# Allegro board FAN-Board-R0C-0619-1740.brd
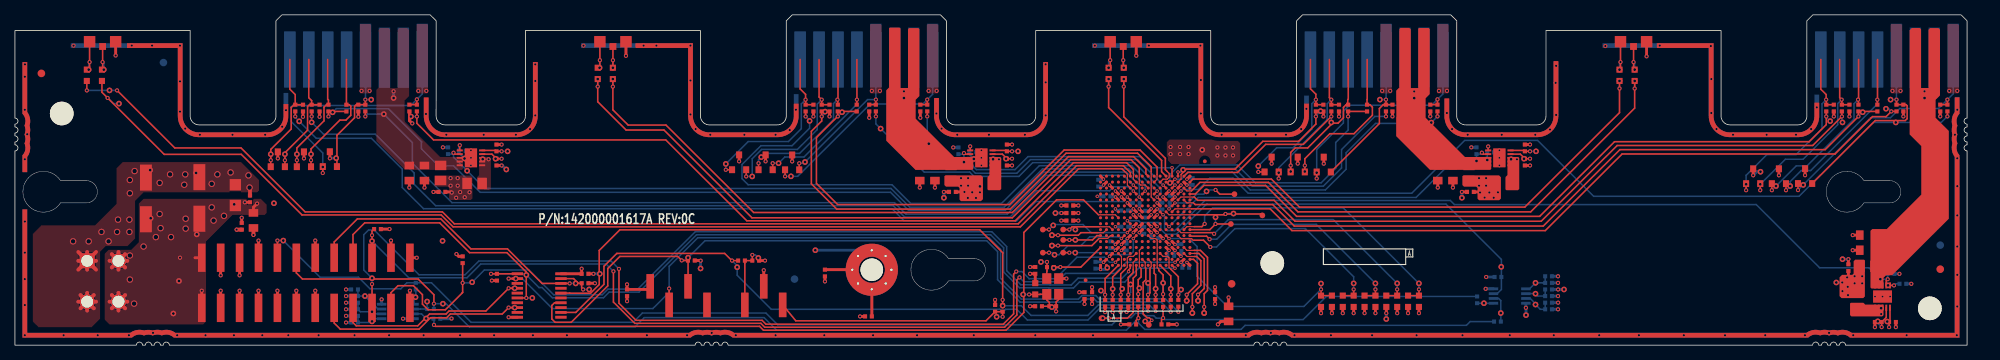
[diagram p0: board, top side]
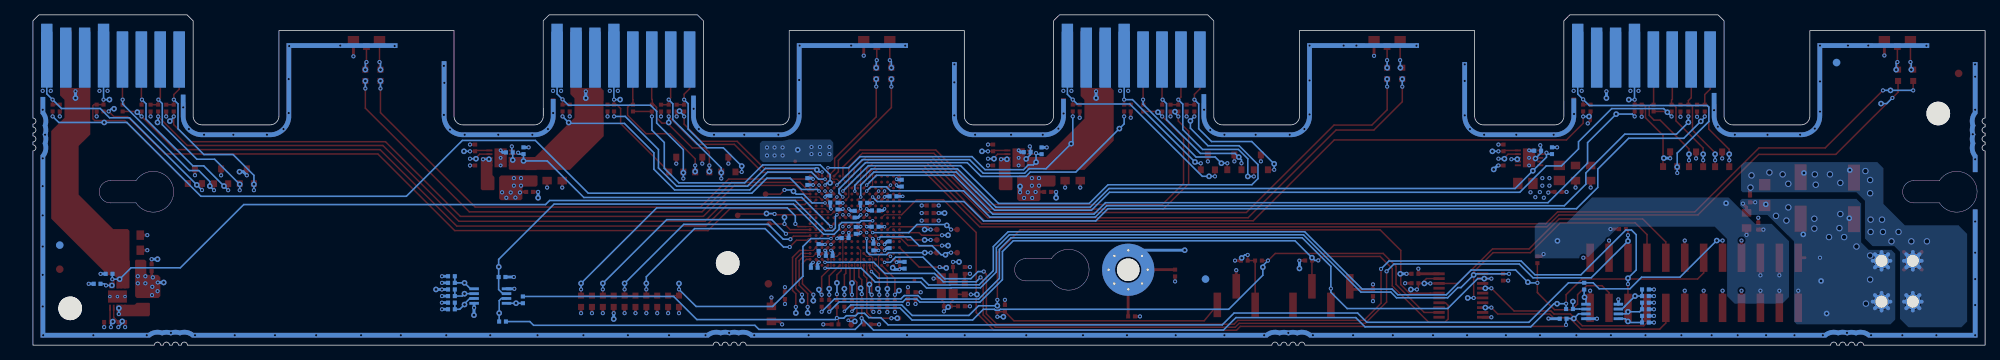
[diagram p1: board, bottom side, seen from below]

Outline 262.04 x 44.46 mm; copper layers: TOP, G2, V3, BOTTOM. Coordinates in mm from the lower left corner of the outline.

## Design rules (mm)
constraint set DEFAULT: min track width 0.203
net group CLS_CTRL-3W: nets CPLD_25MHZ CPLD_25MHZ_R FAN_SCL_1 FAN_SCL_1_R FAN_SDA_1 FAN_SDA_1_R
net group CLS_POWER: nets N66403123
net group CLS_VDD_12V: nets VDD12V

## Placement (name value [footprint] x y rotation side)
BGA1  LCMXO3LF-1300C-5BG256C  [BGA_D8_16C_256SP_14WL]  151.72 16.74 180 top
C1  0.1uF  [CC0402]  151.74 17.63 180 bottom
C2  0.1uF  [CC0402]  154.03 18.72 0 bottom
C3  0.1uF  [CC0402]  151.59 15.44 0 bottom
C4  0.1uF  [CC0402]  155.16 12.03 270 bottom
C5  10nF  [CC0402]  60.06 26.16 90 bottom
C6  10nF  [CC0402]  128.58 25.98 90 bottom
C7  10nF  [CC0402]  198.1 25.94 90 bottom
C8  0.1uF/16V  [CC0402]  64.64 24.64 180 top
C9  0.1uF/16V  [CC0402]  133.16 24.64 180 top
C10  0.1uF/16V  [CC0402]  202.69 24.64 180 top
C11  0.1uF  [CC0402]  150.52 19.15 90 bottom
C12  10uF  [CC0805]  52.95 23.16 0 top
C13  10uF  [CC0805]  54.98 23.16 0 top
C14  10uF  [CC0805]  121.46 23.16 0 top
C15  10uF  [CC0805]  123.49 23.16 0 top
C16  10uF  [CC0805]  191 23.16 0 top
C17  10uF  [CC0805]  193.03 23.16 0 top
C18  0.1uF  [CC0402]  31.56 19.68 0 top
C19  0.1uF  [CC0402]  158.09 22.02 180 bottom
C20  0.1uF  [CC0402]  148.96 18.12 90 bottom
C21  0.1uF/16V  [CC0402]  57.33 20.62 270 top
C22  0.1uF/16V  [CC0402]  125.84 20.62 270 top
C23  0.1uF/16V  [CC0402]  195.38 20.62 270 top
C24  0.1uF  [CC0402]  153.02 14.41 270 bottom
C25  0.1uF  [CC0402]  156.58 13.14 180 bottom
C26  0.1uF  [CC0402]  141.6 18.8 270 top
C27  270uF  [CAPALE_6D3PI_5D6_2SP_6D6WL7D6H]  17.59 19.75 180 top
C28  0.1uF  [CC0402]  147.07 13.51 180 bottom
C29  0.1uF  [CC0402]  141.6 17.78 270 top
C30  22uF  [CC0805]  32.02 16.79 180 top
C31  0.1uF  [CC0402]  141.6 16.76 270 top
C32  0.1uF  [CC0402]  149.22 13.21 0 bottom
C33  0.1uF  [CC0402]  30.45 16 180 top
C34  0.1uF  [CC0402]  155.02 19.66 180 bottom
C35  10uF  [CC0805]  248.65 14.81 270 top
C36  0.1uF  [CC0402]  149 15.94 90 bottom
C37  0.1uF  [CC0402]  157.16 10.43 90 bottom
C38  10uF  [CC0805]  248.65 12.78 270 top
C39  0.1uF  [CC0402]  145.05 10.76 0 bottom
C40  0.1uF  [CC0402]  146.6 20.03 90 bottom
C41  0.1uF/16V  [CC0402]  246.11 10.43 180 top
C42  10nF  [CC0402]  253.43 8.26 90 bottom
C43  0.1uF  [CC0402]  76.53 9.6 90 top
C44  10uF  [CC0805]  162.92 4.21 0 top
C45  0.1uF  [CC0402]  137.41 5.23 270 top
C46  0.1uF  [CC0402]  136.96 10.06 180 top
C47  0.1uF  [CC0402]  143.57 6.67 0 top
C48  0.1uF  [CC0402]  144.59 6.67 0 top
C49  0.1uF  [CC0402]  145.43 21.81 180 bottom
C50  1uF  [CC0402]  161.1 6.67 0 top
C51  0.1uF  [CC0402]  82.17 7.05 180 top
C52  0.1uF/16V  [CC0402]  250.13 3.11 90 top
C53  *270uF  [CAPALE_6D3PI_5D6_2SP_6D6WL7D6H]  24.77 19.81 180 top
C54  *22uF  [CC1206]  29.59 20.19 180 top
CONN1  LCB25-K2424S01C-03  [CONN_2D54X6D75_2X12SP_38D1W9L]  39.05 8.39 0 top
CONN2  MINI-FIT  [CONNF_4D2X5D5_2X2DP_10W9D6L_PIP]  11.8 8.6 180 top
CONN3  HXSPH2.54-S-S-08N5-G/F  [CONN_2D54X2D5_8SP_1NP_20D32W]  94.17 6.67 0 top
CONN4  gold_finger  [GOLD_FINGER_2D54_8X2SP]  36.9 38.45 180 bottom
CONN5  gold_finger  [GOLD_FINGER_2D54_8X2SP]  105.4 38.45 180 bottom
CONN6  gold_finger  [GOLD_FINGER_2D54_8X2SP]  173.9 38.45 180 bottom
CONN7  gold_finger  [GOLD_FINGER_2D54_8X2SP]  242.4 38.45 180 bottom
H7  SKREW  [MTH_276C118D_8DP_OSP]  115.02 10.15 90 top
L1  *100MHz/6A/30ohm  [LC0805]  57.15 23.18 180 top
L2  *100MHz/6A/30ohm  [LC0805]  125.67 23.18 180 top
L3  *100MHz/6A/30ohm  [LC0805]  195.2 23.18 180 top
L4  100MHz/6A/30ohm  [LC0805]  61.71 21.77 90 top
L5  100MHz/6A/30ohm  [LC0805]  130.23 21.77 90 top
L6  100MHz/6A/30ohm  [LC0805]  199.76 21.77 90 top
L7  *100MHz/6A/30ohm  [LC0805]  248.67 10.6 90 top
L8  100MHz/500mA  [LC0603]  136.96 7.58 180 top
L9  100MHz/6A/30ohm  [LC0805]  247.26 6.05 0 top
LED1  LED2_3  [LED_3D5_3SP_1W3L_A_C1_C2]  11.77 40.85 0 top
LED2  LED2_3  [LED_3D5_3SP_1W3L_A_C1_C2]  80.27 40.85 0 top
LED3  LED2_3  [LED_3D5_3SP_1W3L_A_C1_C2]  148.77 40.85 0 top
LED4  LED2_3  [LED_3D5_3SP_1W3L_A_C1_C2]  217.27 40.85 0 top
NOREF  -  []  160.52 41.66 0 top
NOREF#2  -  []  123.04 10.06 0 top
NOREF#3  -  []  0 0 0 top
NOREF#4  -  []  23.52 41.66 0 top
NOREF#5  -  []  7.7 5.85 0 top
NOREF#6  -  []  65.27 5.65 0 top
NOREF#7  -  []  205.52 41.66 0 top
NOREF#8  -  []  56.55 43.66 0 top
NOREF#9  -  []  240.54 43.66 0 top
NOREF#10  -  [unnamed#2]  163.32 8.26 0 top
NOREF#11  -  []  103.54 43.66 0 top
NOREF#12  -  []  172.04 43.66 0 top
NOREF#13  -  []  39.05 8.39 0 top
NOREF#14  -  []  7.57 20.65 0 top
NOREF#15  -  [unnamed#2]  6.29 31.18 0 top
NOREF#16  -  []  35.04 43.66 0 top
NOREF#17  -  []  37.05 8.39 0 top
NOREF#18  -  []  212.62 -88.02 0 top
NOREF#19  -  []  9.7 5.85 0 top
NOREF#20  -  []  115.02 10.15 0 top
NOREF#21  -  [unnamed#2]  258.44 10.22 0 top
NOREF#22  -  []  0 0 0 top
NOREF#23  -  []  70.69 18.92 0 top
NOREF#24  -  [unnamed#2]  257.05 4.95 0 top
NOREF#25  -  []  245.9 20.65 0 top
NOREF#26  -  []  92.02 41.66 0 top
NOREF#27  -  []  338.67 -98.03 0 top
NOREF#28  -  []  193.55 43.66 0 top
NOREF#29  -  []  3.82 20.65 0 top
NOREF#30  -  []  -30.48 -80.01 0 top
NOREF#31  -  []  65.27 5.65 0 top
NOREF#32  -  []  0 0 0 top
NOREF#33  -  []  262.04 43.66 0 top
NOREF#34  -  []  137.02 41.66 0 top
NOREF#35  -  [unnamed#2]  168.78 11.05 0 top
NOREF#36  -  []  246.02 20.5 0 top
NOREF#37  -  []  11.77 40.85 0 top
NOREF#38  -  []  148.77 40.85 0 top
NOREF#39  -  []  217.27 40.85 0 top
NOREF#40  -  []  229.02 41.66 0 top
NOREF#41  -  []  125.04 43.66 0 top
NOREF#42  -  [unnamed#2]  3.56 36.58 0 top
NOREF#43  -  []  68.52 41.66 0 top
NOREF#44  -  []  80.27 40.85 0 top
NOREF#45  -  []  115.02 10.15 0 top
NOREF#46  -  []  217.27 40.85 0 top
NOREF#47  -  [unnamed#2]  19.94 38.04 180 bottom
NOREF#48  -  [unnamed#2]  104.65 8.89 180 bottom
NOREF#49  -  [unnamed#2]  258.44 13.46 180 bottom
OSC1  25MHz  [OSC_1D6X2D12_4SP_2D5W3D2L1DH]  139.31 7.9 90 top
R1  110  [RC0603]  11.68 36.32 0 top
R2  110  [RC0603]  80.26 36.58 0 top
R3  110  [RC0603]  148.84 36.58 0 top
R4  110  [RC0603]  217.42 36.32 0 top
R5  110  [RC0603]  9.65 36.32 0 top
R6  110  [RC0603]  78.23 36.58 0 top
R7  110  [RC0603]  146.81 36.58 0 top
R8  110  [RC0603]  215.39 36.32 0 top
R9  1K  [RC0402]  47.04 31.92 0 top
R10  1K  [RC0402]  53.96 31.92 0 top
R11  1K  [RC0402]  115.57 31.92 0 top
R12  1K  [RC0402]  122.47 31.92 0 top
R13  1K  [RC0402]  184.04 31.92 0 top
R14  1K  [RC0402]  190.96 31.92 0 top
R15  1K  [RC0402]  252.57 31.92 0 top
R16  1K  [RC0402]  259.41 31.92 0 top
R17  1K  [RC0402]  37.63 31.91 0 top
R18  4.7K  [RC0402]  38.67 31.91 0 top
R19  1K  [RC0402]  39.83 31.91 0 top
R20  4.7K  [RC0402]  40.89 31.91 0 top
R21  470  [RC0402]  42.09 31.91 180 top
R22  470  [RC0402]  44.5 31.91 180 top
R23  1K  [RC0402]  106.14 31.91 0 top
R24  4.7K  [RC0402]  107.19 31.91 0 top
R25  1K  [RC0402]  108.3 31.91 0 top
R26  4.7K  [RC0402]  109.35 31.91 0 top
R27  470  [RC0402]  110.46 31.91 180 top
R28  470  [RC0402]  113 31.91 180 top
R29  1K  [RC0402]  174.63 31.91 0 top
R30  4.7K  [RC0402]  175.64 31.91 0 top
R31  1K  [RC0402]  176.7 31.91 0 top
R32  4.7K  [RC0402]  177.74 31.91 0 top
R33  470  [RC0402]  178.96 31.91 180 top
R34  470  [RC0402]  181.5 31.91 180 top
R35  1K  [RC0402]  243.14 31.91 0 top
R36  4.7K  [RC0402]  244.16 31.91 0 top
R37  1K  [RC0402]  245.24 31.91 0 top
R38  4.7K  [RC0402]  246.25 31.91 0 top
R39  470  [RC0402]  247.46 31.91 180 top
R40  470  [RC0402]  250 31.91 180 top
R43  2.2K 1%  [RC0402]  64.64 26.54 0 top
R44  2.2K 1%  [RC0402]  133.16 26.54 0 top
R45  2.2K 1%  [RC0402]  202.69 26.54 0 top
R46  *4.7K  [RC0402]  58.14 26.17 180 bottom
R47  *4.7K  [RC0402]  126.65 26.16 180 bottom
R48  *4.7K  [RC0402]  196.19 26.17 180 bottom
R57  1K  [RC0402]  48.67 15.62 270 top
R58  0  [RC0402]  108.73 9.71 180 top
R59  4.7K  [RC0402]  60.1 11.49 0 top
R61  4.7K  [RC0402]  90.81 11.39 90 top
R62  33  [RC0402]  97.54 11.38 90 top
R63  4.7K  [RC0402]  99.44 11.38 90 top
R64  *4.7K  [RC0402]  251.82 9.6 90 bottom
R65  4.7K  [RC0402]  139.31 5.23 90 top
R66  1K  [RC0402]  64.71 9.14 180 top
R67  33  [RC0402]  138.99 10.5 270 top
R68  4.7K  [RC0402]  76.53 8.33 270 top
R69  *10K  [RC0603]  175.32 5.91 0 top
R70  *4.7K  [RC0603]  176.78 5.91 180 top
R71  *10K  [RC0603]  178.24 5.91 0 top
R72  *4.7K  [RC0603]  179.71 5.91 180 top
R73  *10K  [RC0603]  181.17 5.91 0 top
R74  *4.7K  [RC0603]  182.63 5.91 180 top
R75  *10K  [RC0603]  184.09 5.91 0 top
R76  *4.7K  [RC0603]  185.55 5.91 180 top
R77  *10K  [RC0603]  187.01 5.91 0 top
R78  *4.7K  [RC0603]  188.47 5.91 180 top
R79  0  [RC0402]  114.58 3.87 90 top
R80  4.7K  [RC0402]  146.34 5.63 180 top
R81  4.7K  [RC0402]  147.36 5.63 180 top
R82  4.7K  [RC0402]  148.44 5.63 180 top
R83  4.7K  [RC0402]  149.45 5.63 180 top
R84  33  [RC0402]  150.79 5.63 180 top
R85  33  [RC0402]  152.11 5.63 0 top
R86  33  [RC0402]  153.12 5.63 0 top
R87  33  [RC0402]  155.15 5.63 0 top
R88  33  [RC0402]  156.17 5.63 0 top
R89  33  [RC0402]  154.13 5.61 180 top
R90  10K  [RC0402]  131.57 4.95 180 top
R91  33  [RC0402]  132.59 4.95 0 top
R93  2.2K 1%  [RC0402]  252.03 3.11 270 top
R94  4.7K  [RC0402]  150.05 2.79 270 top
R95  4.7K  [RC0402]  154.37 2.79 90 top
R96  4.7K  [RC0402]  199.08 9.17 270 bottom
R97  4.7K  [RC0402]  205.87 8.38 90 bottom
R98  4.7K  [RC0402]  205.87 7.49 90 bottom
R99  0  [RC0402]  53.82 7.94 180 bottom
R100  0  [RC0402]  196.28 6.1 180 bottom
R101  4.7K  [RC0402]  45.59 6.6 270 bottom
R102  4.7K  [RC0402]  205.87 4.83 270 bottom
R103  0  [RC0402]  55.79 4.86 90 bottom
R104  4.7K  [RC0402]  45.59 5.71 270 bottom
R105  0  [RC0402]  199.01 3.17 270 bottom
R106  4.7K  [RC0402]  56.64 3.56 90 bottom
R107  4.7K  [RC0402]  45.59 3.94 90 bottom
R108  4.7K  [RC0402]  184.91 31.92 0 top
R109  4.7K  [RC0402]  114.68 31.92 0 top
R110  4.7K  [RC0402]  46.1 31.92 0 top
R111  4.7K  [RC0402]  253.49 31.92 0 top
R112  4.7K  [RC0402]  189.99 31.92 0 top
R113  4.7K  [RC0402]  121.54 31.92 0 top
R114  4.7K  [RC0402]  52.96 31.92 0 top
R115  4.7K  [RC0402]  258.44 31.92 0 top
R116  *4.7K  [RC0402]  45.59 7.49 90 bottom
R117  *4.7K  [RC0402]  45.59 3.05 270 bottom
R118  *4.7K  [RC0402]  45.59 4.83 270 bottom
R119  *4.7K  [RC0402]  205.87 6.6 270 bottom
R120  *4.7K  [RC0402]  205.87 9.27 90 bottom
R121  *4.7K  [RC0402]  205.87 5.71 90 bottom
TP1  *NCA  [TP_30C0D0C_OSP]  167.45 17.46 0 top
TP2  *NCA  [TP_30C0D0C_OSP]  163.7 20.32 0 top
TP3  *NCA  [TP_30C0D0C_OSP]  137.99 15.56 180 top
TP4  *NCA  [TP_30C0D0C_OSP]  140.72 15.56 0 top
TP5  *NCA  [TP_30C0D0C_OSP]  163.22 16.31 0 top
TP6  *NCA  [TP_30C0D0C_OSP]  139.19 14.8 0 top
TP7  *NCA  [TP_30C0D0C_OSP]  140.72 14.16 180 top
TP8  *NCA  [TP_30C0D0C_OSP]  139.19 13.4 180 top
TP9  *NCA  [TP_30C0D0C_OSP]  137.99 12.45 180 top
TP10  *NCA  [TP_30C0D0C_OSP]  140.72 12.45 180 top
TP11  *NCA  [TP_30C0D0C_OSP]  157.29 5.97 0 top
TP12  *NCA  [TP_30C0D0C_OSP]  158.81 5.97 0 top
TP13  *NCA  [TP_30C0D0C_OSP]  158.05 4.32 0 top
TP14  *NCA  [TP_30C0D0C_OSP]  159.64 4.32 0 top
TP15  *NCA  [TP_30C0D0C_OSP]  145.86 3.62 180 top
TP16  *NCA  [TP_30C0D0C_OSP]  152.21 2.73 180 top
U1  SY6875ADBC  [DFN_D5X3D_10SP_3WL1H_G1]  61.21 25.21 90 top
U2  SY6875ADBC  [DFN_D5X3D_10SP_3WL1H_G1]  129.73 25.21 90 top
U3  SY6875ADBC  [DFN_D5X3D_10SP_3WL1H_G1]  199.26 25.21 90 top
U4  PSOT03C  [SOT23_1D9X2D_3SP_1D3W2D92L1D11H]  97.21 24.61 0 top
U5  PSOT03C  [SOT23_1D9X2D_3SP_1D3W2D92L1D11H]  100.77 24.61 0 top
U6  PSOT03C  [SOT23_1D9X2D_3SP_1D3W2D92L1D11H]  104.33 24.6 0 top
U7  PSOT03C  [SOT23_1D9X2D_3SP_1D3W2D92L1D11H]  168.69 24.31 0 top
U8  PSOT03C  [SOT23_1D9X2D_3SP_1D3W2D92L1D11H]  172.2 24.31 0 top
U9  PSOT03C  [SOT23_1D9X2D_3SP_1D3W2D92L1D11H]  175.69 24.31 0 top
U10  PSOT03C  [SOT23_1D9X2D_3SP_1D3W2D92L1D11H]  42.28 25.03 0 top
U11  PSOT03C  [SOT23_1D9X2D_3SP_1D3W2D92L1D11H]  35.29 25.02 0 top
U12  PSOT03C  [SOT23_1D9X2D_3SP_1D3W2D92L1D11H]  38.8 25.02 0 top
U13  PSOT03C  [SOT23_1D9X2D_3SP_1D3W2D92L1D11H]  240.3 22.75 0 top
U14  PSOT03C  [SOT23_1D9X2D_3SP_1D3W2D92L1D11H]  233.33 22.74 0 top
U15  PSOT03C  [SOT23_1D9X2D_3SP_1D3W2D92L1D11H]  236.79 22.74 0 top
U16  SN74LVC244APWR  [TSSOP_D65X5D88_20SP_6D5L]  70.37 6.68 0 top
U17  SY6875ADBC  [DFN_D5X3D_10SP_3WL1H_G1]  250.7 6.54 0 top
U18  TMP75AIDGK  [SOP_D65X4D35_8SP_3WL]  200.65 6.61 0 bottom
U19  TMP75AIDGK  [SOP_D65X4D35_8SP_3WL]  51.4 4.53 180 bottom

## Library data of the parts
BGA1 = CPLD_LATTICE_LCMXO3L_caBGA256
C1-C7 C11-C20 C24-C26 C28-C40 C42 C44-C51 C54 = C_NP
C8-C10 C21-C23 C41 C52 = CAP NP: room: 35
C27 C53 = C_P
C43 = C_NP: room: 71
CONN1 = PIN HEADER_MALE_12PX2R
CONN2 = CONN_POWER_FEMALE_2PX2R
CONN3 = PINSTICK_MALE_8PX1R_VOID5
CONN4-CONN7 = CONN_2
H7 = SKREW
L1-L9 = BEAD: room: 8
LED1-LED4 = LED2_3
OSC1 = OSC_10
R1-R8 = R_0: room: 55
R9-R17 R19 R23 R25 R29 R31 R35 R37 R46-R48 R57-R59 R64 R66-R68 R79 R84-R90 R94-R107 R116-R121 = R: tolerance: 1%
R18 R20 R24 R26 R30 R32 R36 R38 R43-R45 R62 R69 R71 R73 R75 R77 R91 R93 R108-R115 = R
R21 R22 R27 R28 R33 R34 R39 R40 = R: room: 1
R61 R63 R65 R70 R72 R74 R76 R78 R80-R83 = R: tolerance: 1%; room: U83
TP1-TP16 = NCA: room: 9
U1-U3 U17 = MONITOR_CUR_SILERGY_SY6875
U4-U15 = TVS3_1
U16 = LOGIC_TI_SN74LVC244A
U18 U19 = TEMP SENSOR_TI_TMP75

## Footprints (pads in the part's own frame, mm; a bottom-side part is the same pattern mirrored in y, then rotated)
BGA_D8_16C_256SP_14WL
  round 0.508 smd: (-8,-8) (8,8)
  round 0.406 smd: A1(-6,6) A2(-5.2,6) A3(-4.4,6) A4(-3.6,6) A5(-2.8,6) A6(-2,6) A7(-1.2,6) A8(-0.4,6) A9(0.4,6) A10(1.2,6) A11(2,6) A12(2.8,6) A13(3.6,6) A14(4.4,6) A15(5.2,6) A16(6,6) B1(-6,5.2) B2(-5.2,5.2) B3(-4.4,5.2) B4(-3.6,5.2) B5(-2.8,5.2) B6(-2,5.2) B7(-1.2,5.2) B8(-0.4,5.2) B9(0.4,5.2) B10(1.2,5.2) B11(2,5.2) B12(2.8,5.2) B13(3.6,5.2) B14(4.4,5.2) B15(5.2,5.2) B16(6,5.2) C1(-6,4.4) C2(-5.2,4.4) C3(-4.4,4.4) C4(-3.6,4.4) C5(-2.8,4.4) C6(-2,4.4) C7(-1.2,4.4) C8(-0.4,4.4) C9(0.4,4.4) C10(1.2,4.4) C11(2,4.4) C12(2.8,4.4) C13(3.6,4.4) C14(4.4,4.4) C15(5.2,4.4) C16(6,4.4) D1(-6,3.6) D2(-5.2,3.6) D3(-4.4,3.6) D4(-3.6,3.6) D5(-2.8,3.6) D6(-2,3.6) D7(-1.2,3.6) D8(-0.4,3.6) D9(0.4,3.6) D10(1.2,3.6) D11(2,3.6) D12(2.8,3.6) D13(3.6,3.6) D14(4.4,3.6) D15(5.2,3.6) D16(6,3.6) E1(-6,2.8) E2(-5.2,2.8) E3(-4.4,2.8) E4(-3.6,2.8) E5(-2.8,2.8) E6(-2,2.8) E7(-1.2,2.8) E8(-0.4,2.8) E9(0.4,2.8) E10(1.2,2.8) E11(2,2.8) E12(2.8,2.8) E13(3.6,2.8) E14(4.4,2.8) E15(5.2,2.8) E16(6,2.8) F1(-6,2) F2(-5.2,2) F3(-4.4,2) F4(-3.6,2) F5(-2.8,2) F6(-2,2) F7(-1.2,2) F8(-0.4,2) F9(0.4,2) F10(1.2,2) F11(2,2) F12(2.8,2) F13(3.6,2) F14(4.4,2) F15(5.2,2) F16(6,2) G1(-6,1.2) G2(-5.2,1.2) G3(-4.4,1.2) G4(-3.6,1.2) G5(-2.8,1.2) G6(-2,1.2) G7(-1.2,1.2) G8(-0.4,1.2) G9(0.4,1.2) G10(1.2,1.2) G11(2,1.2) G12(2.8,1.2) G13(3.6,1.2) G14(4.4,1.2) G15(5.2,1.2) G16(6,1.2) H1(-6,0.4) H2(-5.2,0.4) H3(-4.4,0.4) H4(-3.6,0.4) H5(-2.8,0.4) H6(-2,0.4) H7(-1.2,0.4) H8(-0.4,0.4) H9(0.4,0.4) H10(1.2,0.4) H11(2,0.4) H12(2.8,0.4) H13(3.6,0.4) H14(4.4,0.4) H15(5.2,0.4) H16(6,0.4) J1(-6,-0.4) J2(-5.2,-0.4) J3(-4.4,-0.4) J4(-3.6,-0.4) J5(-2.8,-0.4) J6(-2,-0.4) J7(-1.2,-0.4) J8(-0.4,-0.4) J9(0.4,-0.4) J10(1.2,-0.4) J11(2,-0.4) J12(2.8,-0.4) J13(3.6,-0.4) J14(4.4,-0.4) J15(5.2,-0.4) J16(6,-0.4) K1(-6,-1.2) K2(-5.2,-1.2) K3(-4.4,-1.2) K4(-3.6,-1.2) K5(-2.8,-1.2) K6(-2,-1.2) K7(-1.2,-1.2) K8(-0.4,-1.2) K9(0.4,-1.2) K10(1.2,-1.2) K11(2,-1.2) K12(2.8,-1.2) K13(3.6,-1.2) K14(4.4,-1.2) K15(5.2,-1.2) K16(6,-1.2) L1(-6,-2) L2(-5.2,-2) L3(-4.4,-2) L4(-3.6,-2) L5(-2.8,-2) L6(-2,-2) L7(-1.2,-2) L8(-0.4,-2) L9(0.4,-2) L10(1.2,-2) L11(2,-2) L12(2.8,-2) L13(3.6,-2) L14(4.4,-2) L15(5.2,-2) L16(6,-2) M1(-6,-2.8) M2(-5.2,-2.8) M3(-4.4,-2.8) M4(-3.6,-2.8) M5(-2.8,-2.8) M6(-2,-2.8) M7(-1.2,-2.8) M8(-0.4,-2.8) M9(0.4,-2.8) M10(1.2,-2.8) M11(2,-2.8) M12(2.8,-2.8) M13(3.6,-2.8) M14(4.4,-2.8) M15(5.2,-2.8) M16(6,-2.8) N1(-6,-3.6) N2(-5.2,-3.6) N3(-4.4,-3.6) N4(-3.6,-3.6) N5(-2.8,-3.6) N6(-2,-3.6) N7(-1.2,-3.6) N8(-0.4,-3.6) N9(0.4,-3.6) N10(1.2,-3.6) N11(2,-3.6) N12(2.8,-3.6) N13(3.6,-3.6) N14(4.4,-3.6) N15(5.2,-3.6) N16(6,-3.6) P1(-6,-4.4) P2(-5.2,-4.4) P3(-4.4,-4.4) P4(-3.6,-4.4) P5(-2.8,-4.4) P6(-2,-4.4) P7(-1.2,-4.4) P8(-0.4,-4.4) P9(0.4,-4.4) P10(1.2,-4.4) P11(2,-4.4) P12(2.8,-4.4) P13(3.6,-4.4) P14(4.4,-4.4) P15(5.2,-4.4) P16(6,-4.4) R1(-6,-5.2) R2(-5.2,-5.2) R3(-4.4,-5.2) R4(-3.6,-5.2) R5(-2.8,-5.2) R6(-2,-5.2) R7(-1.2,-5.2) R8(-0.4,-5.2) R9(0.4,-5.2) R10(1.2,-5.2) R11(2,-5.2) R12(2.8,-5.2) R13(3.6,-5.2) R14(4.4,-5.2) R15(5.2,-5.2) R16(6,-5.2) T1(-6,-6) T2(-5.2,-6) T3(-4.4,-6) T4(-3.6,-6) T5(-2.8,-6) T6(-2,-6) T7(-1.2,-6) T8(-0.4,-6) T9(0.4,-6) T10(1.2,-6) T11(2,-6) T12(2.8,-6) T13(3.6,-6) T14(4.4,-6) T15(5.2,-6) T16(6,-6)
CAPALE_6D3PI_5D6_2SP_6D6WL7D6H
  rect 1.6x3.505 smd: A(0,-2.8) C(0,2.8)
CC0402
  rect 0.559x0.539 smd: 1(0,0.454) 2(0,-0.454)
CC0805
  rect 1.27x1.016 smd: 1(0,1.016) 2(0,-1.016)
CC1206
  rect 1.524x1.524 smd: 1(0,1.397) 2(0,-1.397)
CONN_2D54X2D5_8SP_1NP_20D32W
  rect 1.016x3.302 smd: 1(-8.89,1.25) 2(-6.35,-1.25) 3(-3.81,1.25) 4(-1.27,-1.25) 6(3.81,-1.25) 7(6.35,1.25) 8(8.89,-1.25)
CONN_2D54X6D75_2X12SP_38D1W9L
  rect 1.016x3.81 smd: 1(-13.97,-3.375) 2(-13.97,3.375) 3(-11.43,-3.375) 4(-11.43,3.375) 5(-8.89,-3.375) 6(-8.89,3.375) 7(-6.35,-3.375) 8(-6.35,3.375) 9(-3.81,-3.375) 10(-3.81,3.375) 11(-1.27,-3.375) 12(-1.27,3.375) 13(1.27,-3.375) 14(1.27,3.375) 15(3.81,-3.375) 16(3.81,3.375) 17(6.35,-3.375) 18(6.35,3.375) 19(8.89,-3.375) 20(8.89,3.375) 21(11.43,-3.375) 22(11.43,3.375) 23(13.97,-3.375) 24(13.97,3.375)
CONNF_4D2X5D5_2X2DP_10W9D6L_PIP
  rect 2.032x2.032 hole 1.6: 1(2.1,-2.75)
  round 2.032 hole 1.6: 2(-2.1,-2.75) 3(2.1,2.75) 4(-2.1,2.75)
DFN_D5X3D_10SP_3WL1H_G1
  rect 0.254x0.813 smd: 1(-1,-1.5) 2(-0.5,-1.5) 3(0,-1.5) 4(0.5,-1.5) 5(1,-1.5) 6(1,1.5) 7(0.5,1.5) 8(0,1.5) 9(-0.5,1.5) 10(-1,1.5)
  rect 2.54x1.651 smd: G1(0,0)
GOLD_FINGER_2D54_8X2SP
  rect 1.524x7.518 smd: 1(0,0) 2(-2.54,0) 3(-5.08,0) 4(-7.62,0) 9(0,0) 10(-2.54,0) 11(-5.08,0) 12(-7.62,0) 13(-10.16,0) 14(-12.7,0) 15(-15.24,0) 16(-17.78,0)
  rect 1.524x8.56 smd: 5(-10.16,0.533) 8(-17.78,0.533)
  rect 1.524x8.052 smd: 6(-12.7,0.267) 7(-15.24,0.267)
LC0603
  rect 0.813x0.813 smd: 1(0,0.762) 2(0,-0.762)
LC0805
  rect 1.524x1.27 smd: 1(0,1.016) 2(0,-1.016)
LED_3D5_3SP_1W3L_A_C1_C2
  rect 1.524x1.524 smd: A(1.75,0) C1(-1.75,0)
  rect 0.914x0.914 smd: C2(0,-0.65)
MTH_276C118D_8DP_OSP
  round 2.997 hole 2.997 unplated: (0,0)
  round 0.889 hole 0.305: 1(0,2.629) 2(1.859,1.859) 3(2.629,0) 4(1.859,-1.859) 5(0,-2.629) 6(-1.859,-1.859) 7(-2.629,0) 8(-1.859,1.859)
OSC_1D6X2D12_4SP_2D5W3D2L1DH
  rect 1.422x1.219 smd: 1(-1.06,-0.8) 2(1.06,-0.8) 3(1.06,0.8) 4(-1.06,0.8)
RC0402
  rect 0.559x0.539 smd: 1(0,0.454) 2(0,-0.454)
RC0603
  rect 0.813x0.813 smd: 1(0,0.762) 2(0,-0.762)
SOP_D65X4D35_8SP_3WL
  rect 1.27x0.381 smd: 1(-2.175,0.975) 2(-2.175,0.325) 3(-2.175,-0.325) 4(-2.175,-0.975) 5(2.175,-0.975) 6(2.175,-0.325) 7(2.175,0.325) 8(2.175,0.975)
SOT23_1D9X2D_3SP_1D3W2D92L1D11H
  rect 0.813x0.914 smd: A(0,1) C1(-0.95,-1) C2(0.95,-1)
TP_30C0D0C_OSP
  round 0.762 smd: 1(0,0)
TSSOP_D65X5D88_20SP_6D5L
  rect 1.524x0.381 smd: 1(-2.926,2.926) 2(-2.926,2.276) 3(-2.926,1.626) 4(-2.926,0.975) 5(-2.926,0.325) 6(-2.926,-0.325) 7(-2.926,-0.975) 8(-2.926,-1.626) 9(-2.926,-2.276) 10(-2.926,-2.926) 11(2.926,-2.926) 12(2.926,-2.276) 13(2.926,-1.626) 14(2.926,-0.975) 15(2.926,-0.325) 16(2.926,0.325) 17(2.926,0.975) 18(2.926,1.626) 19(2.926,2.276) 20(2.926,2.926)
unnamed#2
  round 1.016 smd: (0,0)

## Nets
GND: BGA1.B2(GND/GND/GND_1) BGA1.B15(GND/GND/GND_2) BGA1.C3(GND/GND/GND_3) BGA1.C14(GND/GND/GND_4) BGA1.D4(GND/GND/GND_5) BGA1.D13(GND/GND/GND_6) BGA1.E5(GND/GND/GND_7) BGA1.E12(GND/GND/GND_8) BGA1.F6(GND/GND/GND_9) BGA1.F11(GND/GND/GND_10) BGA1.H8(GND/GND/GND_11) BGA1.H9(GND/GND/GND_12) BGA1.J8(GND/GND/GND_13) BGA1.J9(GND/GND/GND_14) BGA1.L6(GND/GND/GND_15) BGA1.L11(GND/GND/GND_16) BGA1.M5(GND/GND/GND_17) BGA1.M12(GND/GND/GND_18) BGA1.N4(GND/GND/GND_19) BGA1.N13(GND/GND/GND_20) BGA1.P3(GND/GND/GND_21) BGA1.P14(GND/GND/GND_22) BGA1.R2(GND/GND/GND_23) BGA1.R15(GND/GND/GND_24) C1.2 C2.2 C3.2 C4.2 C5.1 C6.1 C7.1 C8.1 C9.1 C10.1 C11.2 C12.2 C13.2 C14.2 C15.2 C16.2 C17.2 C18.2 C19.2 C20.2 C21.2 C22.2 C23.2 C24.2 C25.2 C26.2 C27.C C28.2 C29.2 C30.2 C31.2 C32.2 C33.2 C34.2 C35.2 C36.2 C37.2 C38.2 C39.2 C40.2 C41.2 C42.1 C43.2 C44.2 C45.2 C46.2 C47.2 C48.2 C49.2 C50.2 C51.1 C52.1 C53.C C54.1 CONN1.1 CONN1.2 CONN1.7 CONN1.8 CONN1.9 CONN1.11 CONN1.13 CONN1.14 CONN1.22 CONN1.23 CONN1.24 CONN2.2 CONN2.4 CONN3.7 CONN4.5(C5) CONN4.8(C8) CONN5.5(C5) CONN5.8(C8) CONN6.5(C5) CONN6.8(C8) CONN7.5(C5) CONN7.8(C8) OSC1.2(GND) R43.1 R44.1 R45.1 R58.1 R69.2 R71.2 R73.2 R75.2 R77.2 R79.1 R90.2 R93.1 R98.1 R101.1 R117.1 R118.1 R120.1 R121.1 U1.G1 U2.G1 U3.G1 U4.A U5.A U6.A U7.A U8.A U9.A U10.A U11.A U12.A U13.A U14.A U15.A U16.10(GND) U17.G1 U18.4(GND) U19.4(GND)
VCC_12P_FAN1: C16.1 C17.1 CONN6.6(C6) CONN6.7(C7) L3.2 U3.8(OUT8) U3.9(OUT9) U3.10(OUT0)
VCC_12P_FAN2: C14.1 C15.1 CONN5.6(C6) CONN5.7(C7) L2.2 U2.8(OUT8) U2.9(OUT9) U2.10(OUT0)
VCC_12P_FAN3: C12.1 C13.1 CONN4.6(C6) CONN4.7(C7) L1.2 U1.8(OUT8) U1.9(OUT9) U1.10(OUT0)
VCC_12P_FAN4: C35.1 C38.1 CONN7.6(C6) CONN7.7(C7) L7.2 U17.8(OUT8) U17.9(OUT9) U17.10(OUT0)
VCC_CL_FAN1: L6.2 U3.1(IN1) U3.2(IN2) U3.3(IN3)
VCC_CL_FAN2: L5.2 U2.1(IN1) U2.2(IN2) U2.3(IN3)
VCC_CL_FAN3: L4.2 U1.1(IN1) U1.2(IN2) U1.3(IN3)
VCC_CL_FAN4: L9.2 U17.1(IN1) U17.2(IN2) U17.3(IN3)
VDD12V: C18.1 C21.1 C22.1 C23.1 C27.A C41.1 C53.A C54.2 CONN2.1 CONN2.3 L1.1 L2.1 L3.1 L4.1 L5.1 L6.1 L7.1 L9.1
25MHZ_EN: OSC1.1(\\S\T/OE) R65.2
BOARD_ID_1: BGA1.F3(PL4A/PL7A/PL8A) R71.1 R72.2
BOARD_ID_2: BGA1.F1(PL4B/PL7B/PL8B) R73.1 R74.2
CPLD_25MHZ: BGA1.D16(PR2A/PR3A/PR3A || R_GPLLT_IN**) R67.1
CPLD_25MHZ_R: OSC1.3(OUT) R67.2
CPLD_TCK: BGA1.A7(PT16C/PT15C/PT17C || TCK) R86.1
CPLD_TDI: BGA1.A6(PT12D/PT13D/PT14D || TDI) R87.1
CPLD_TDO: BGA1.C6(PT12C/PT13C/PT14C || TDO) R88.1
CPLD_TMS: BGA1.B8(PT16D/PT15D/PT17D || TMS) R85.1
CPLD_UPD_DISABLE: BGA1.A4(PT10A*/PT10A*/PT10A*) R66.2 U16.1(1O\\\E)
EN_FAN1: BGA1.H5(PL9C/PL13C/PL15C) R48.2 U3.7(EN)
EN_FAN2: BGA1.T4(PB3B/PB3B/PB4B) R47.2 U2.7(EN)
EN_FAN3: BGA1.N9(PB16D/PB18B/PB21B) R46.2 U1.7(EN)
EN_FAN4: BGA1.K6(PL10D/PL14D/PL16D) R64.2 U17.7(EN)
FAN1_DET: BGA1.R4(PB6D/PB6B/PB7B) R14.2
FAN1_DET_R: CONN6.16(C16) R14.1 R112.1 U9.C1
FAN1_DIR: BGA1.T3(PB6C/PB6A/PB7A) R13.2
FAN1_DIR_R: CONN6.13(C13) R13.1 R108.1 U9.C2
FAN1_IN_PWM: CONN6.4(C4) R34.2 U8.C2
FAN1_LED_G: BGA1.R6(PB6B/PB7B/PB9B) R3.2
FAN1_LED_G_R: LED3.C2 R3.1
FAN1_LED_R: BGA1.T5(PB6A/PB7A/PB9A) R7.2
FAN1_LED_R_R: LED3.C1 R7.1
FAN1_OUT_PWM: CONN6.3(C3) R33.2 U8.C1
FAN1_PWM: BGA1.P4(PB3A/PB3A/PB4A) R33.1 R34.1
FAN1_SENSOR: BGA1.T2(PB3C/PB3C/PB4C) R31.2
FAN1_SENSOR_R: CONN6.2(C2) R31.1 R32.1 U7.C2
FAN1_VCP: C10.2 U3.4(VCP)
FAN1R_SENSOR: BGA1.R3(PB3D/PB3D/PB4D) R29.2
FAN1R_SENSOR_R: CONN6.1(C1) R29.1 R30.1 U7.C1
FAN2_DET: BGA1.P5(PB5B/PB4B/PB6B) R12.2
FAN2_DET_R: CONN5.16(C16) R12.1 R113.1 U6.C1
FAN2_DIR: BGA1.M6(PB11C/PB12A/PB15A) R11.2
FAN2_DIR_R: CONN5.13(C13) R11.1 R109.1 U6.C2
FAN2_IN_PWM: CONN5.4(C4) R28.2 U5.C2
FAN2_LED_G: BGA1.T8(PB12B/PB15B/PB18B) R2.2
FAN2_LED_G_R: LED2.C2 R2.1
FAN2_LED_R: BGA1.P8(PB12A/PB15A/PB18A) R6.2
FAN2_LED_R_R: LED2.C1 R6.1
FAN2_OUT_PWM: CONN5.3(C3) R27.2 U5.C1
FAN2_PWM: BGA1.R7(PB9A/PB10A/PB13A) R27.1 R28.1
FAN2_SENSOR: BGA1.M7(PB9C/PB10C/PB13C) R25.2
FAN2_SENSOR_R: CONN5.2(C2) R25.1 R26.1 U4.C2
FAN2_VCP: C9.2 U2.4(VCP)
FAN2R_SENSOR: BGA1.N7(PB9D/PB10D/PB13D) R23.2
FAN2R_SENSOR_R: CONN5.1(C1) R23.1 R24.1 U4.C1
FAN3_DET: BGA1.R10(PB19B/PB23B/PB29B) R10.2
FAN3_DET_R: CONN4.16(C16) R10.1 R114.1 U10.C1
FAN3_DIR: BGA1.P10(PB19A/PB23A/PB29A) R9.2
FAN3_DIR_R: CONN4.13(C13) R9.1 R110.1 U10.C2
FAN3_IN_PWM: CONN4.4(C4) R22.2 U12.C2
FAN3_LED_G: BGA1.P11(PB21B/PB24B/PB31B) R1.2
FAN3_LED_G_R: LED1.C2 R1.1
FAN3_LED_R: BGA1.T11(PB21A/PB24A/PB31A) R5.2
FAN3_LED_R_R: LED1.C1 R5.1
FAN3_OUT_PWM: CONN4.3(C3) R21.2 U12.C1
FAN3_PWM: BGA1.M9(PB18C/PB21C/PB26C) R21.1 R22.1
FAN3_SENSOR: BGA1.N10(PB19C/PB23C/PB28A) R19.2
FAN3_SENSOR_R: CONN4.2(C2) R19.1 R20.1 U11.C2
FAN3_VCP: C8.2 U1.4(VCP)
FAN3R_SENSOR: BGA1.M11(PB19D/PB23D/PB28B) R17.2
FAN3R_SENSOR_R: CONN4.1(C1) R17.1 R18.1 U11.C1
FAN4_DET: BGA1.N3(PL14B/PL20B/PL25B) R16.2
FAN4_DET_R: CONN7.16(C16) R16.1 R115.1 U13.C1
FAN4_DIR: BGA1.K4(PL11C/PL16C/PL19C) R15.2
FAN4_DIR_R: CONN7.13(C13) R15.1 R111.1 U13.C2
FAN4_IN_PWM: CONN7.4(C4) R40.2 U15.C2
FAN4_LED_G: BGA1.P2(PL14D/PL20D/PL25D) R4.2
FAN4_LED_G_R: LED4.C2 R4.1
FAN4_LED_R: BGA1.R1(PL14C/PL20C/PL25C) R8.2
FAN4_LED_R_R: LED4.C1 R8.1
FAN4_OUT_PWM: CONN7.3(C3) R39.2 U15.C1
FAN4_PWM: BGA1.M2(PL14A/PL20A/PL25A) R39.1 R40.1
FAN4_SENSOR: BGA1.M3(PL13A/PL19A/PL24A) R37.2
FAN4_SENSOR_R: CONN7.2(C2) R37.1 R38.1 U14.C2
FAN4_VCP: C52.2 U17.4(VCP)
FAN4R_SENSOR: BGA1.N1(PL13B/PL19B/PL24B) R35.2
FAN4R_SENSOR_R: CONN7.1(C1) R35.1 R36.1 U14.C1
FAN_IDLE: BGA1.A11(PT21A*/PT24A*/PT28A*) CONN1.21 R59.2
FAN_INTERRUPT: BGA1.B13(PT22C/PT26A*/PT34A*) CONN1.19
FAN_SCL_1: CONN1.12 R84.1 R94.1 R103.1 R105.1
FAN_SCL_1_R: BGA1.D9(PT18B*/PT20B*/PT22B*) R84.2
FAN_SDA_1: CONN1.10 R89.1 R95.1 R99.1 R100.1
FAN_SDA_1_R: BGA1.F8(PT18A*/PT20A*/PT22A*) R89.2
FANCARD_CPLD_TCK: CONN1.17 U16.4(1A2)
FANCARD_CPLD_TCK_Y: R86.2 R91.1 U16.16(1Y2)
FANCARD_CPLD_TDI: CONN1.18 U16.6(1A3)
FANCARD_CPLD_TDI_Y: CONN3.3 R61.1 R87.2 U16.14(1Y3)
FANCARD_CPLD_TDO: CONN1.16 U16.18(1Y1)
FANCARD_CPLD_TDO_Y: CONN3.2 R88.2 U16.2(1A1)
FANCARD_CPLD_TMS: CONN1.15 U16.8(1A4)
FANCARD_CPLD_TMS_Y: R62.1 R85.2 U16.12(1Y4)
FANCARD_RST_N: BGA1.B3(PT9C/PT9C/PT9C) CONN1.20 R57.2
ILIM_FAN1: R45.2 U3.5(ILIM)
ILIM_FAN2: R44.2 U2.5(ILIM)
ILIM_FAN3: R43.2 U1.5(ILIM)
ILIM_FAN4: R93.2 U17.5(ILIM)
JTAG_TCK_R: CONN3.8 R90.1 R91.2
JTAG_TMS_R: CONN3.6 R62.2 R63.1
SST_FAN1: C7.2 U3.6(SST)
SST_FAN2: C6.2 U2.6(SST)
SST_FAN3: C5.2 U1.6(SST)
SST_FAN4: C42.2 U17.6(SST)
TEMP_SENSOR_ALERT_1: BGA1.H11(PR9C/PR13C/PR16C) R96.2 U18.3(ALERT)
TEMP_SENSOR_ALERT_2: BGA1.J13(PR9D/PR13D/PR16D) R106.2 U19.3(ALERT)
VERSION_ID_1: BGA1.G2(PL5A/PL8A/PL9A) R77.1 R78.2
VERSION_ID_2: BGA1.G3(PL5B/PL8B/PL9B) R75.1 R76.2
VERSION_ID_3: BGA1.F5(PL5C/PL8C/PL9C) R69.1 R70.2
VSTB_3V3: BGA1.A1(VCC/VCC/VCC_1) BGA1.A16(VCC/VCC/VCC_2) BGA1.D5(VCCIO0/VCCIO0/VCCIO0_1) BGA1.D12(VCCIO0/VCCIO0/VCCIO0_2) BGA1.E4(VCCIO5/VCCIO5/VCCIO5) BGA1.E13(VCCIO1/VCCIO1/VCCIO1_1) BGA1.G7(VCC/VCC/VCC_3) BGA1.G8(VCCIO0/VCCIO0/VCCIO0_3) BGA1.G9(VCCIO0/VCCIO0/VCCIO0_4) BGA1.G10(VCC/VCC/VCC_4) BGA1.H7(VCCIO4/VCCIO4/VCCIO4_1) BGA1.H10(VCCIO1/VCCIO1/VCCIO1_2) BGA1.J7(VCCIO4/VCCIO4/VCCIO4_2) BGA1.J10(VCCIO1/VCCIO1/VCCIO1_3) BGA1.K7(VCC/VCC/VCC_5) BGA1.K8(VCCIO2/VCCIO2/VCCIO2_1) BGA1.K9(VCCIO2/VCCIO2/VCCIO2_2) BGA1.K10(VCC/VCC/VCC_6) BGA1.M4(VCCIO3/VCCIO3/VCCIO3) BGA1.M13(VCCIO1/VCCIO1/VCCIO1_4) BGA1.N5(VCCIO2/VCCIO2/VCCIO2_3) BGA1.N12(VCCIO2/VCCIO2/VCCIO2_4) BGA1.T1(VCC/VCC/VCC_7) BGA1.T16(VCC/VCC/VCC_8) C1.1 C2.1 C3.1 C4.1 C11.1 C19.1 C20.1 C24.1 C25.1 C26.1 C28.1 C29.1 C30.1 C31.1 C32.1 C33.1 C34.1 C36.1 C37.1 C39.1 C40.1 C43.1 C44.1 C46.1 C47.1 C48.1 C49.1 C50.1 C51.2 CONN1.3 CONN1.4 CONN1.5 CONN1.6 CONN3.1 L8.2 LED1.A LED2.A LED3.A LED4.A R18.2 R20.2 R24.2 R26.2 R30.2 R32.2 R36.2 R38.2 R46.1 R47.1 R48.1 R57.1 R59.1 R61.2 R63.2 R64.1 R66.1 R68.1 R70.1 R72.1 R74.1 R76.1 R78.1 R80.1 R81.1 R82.1 R83.1 R94.2 R95.2 R96.1 R97.1 R102.2 R104.1 R106.1 R107.2 R108.2 R109.2 R110.2 R111.2 R112.2 R113.2 R114.2 R115.2 R116.2 R119.2 U16.20(VCC) U18.8(VCC) U19.8(VCC)
VSTB_3V3_25M_VCC: C45.1 L8.1 OSC1.4(VDD) R65.1
N66403123: H7.1 H7.2 H7.3 H7.4 H7.5 H7.6 H7.7 H7.8 R58.2 R79.2
N66410905: R105.2 U18.2(SCL)
N66410909: R100.2 U18.1(SDA)
N66410919: R103.2 U19.2(SCL)
N66410923: R99.2 U19.1(SDA)
N66487659: R68.2 U16.19(2O\\\E)
N66707807: BGA1.C10(PT20C/PT23C/PT27C || JTAGENB) R82.2
N66707810: BGA1.B10(PT20D/PT23D/PT27D || PROGRAMN) R83.2
N66708102: BGA1.A13(PT24C/PT28C/PT36C || INITN) R80.2
N66708112: BGA1.C13(PT24D/PT28D/PT36D || DONE) R81.2
N66771338: BGA1.B9(PT19A*/PT21A*/PT25A*) TP16.1
N66771341: BGA1.A10(PT19B*/PT21B*/PT25B*) TP15.1
N66771344: BGA1.F10(PT21C/PT24C/PT32A*) TP10.1
N66771524: BGA1.F12(PR4C/PR6C/PR7C) TP9.1
N66771539: BGA1.G11(PR5C/PR8C/PR10C) TP3.1
N66771544: BGA1.F14(PR4A/PR6A/PR7A) TP8.1
N66771549: BGA1.F16(PR4B/PR6B/PR7B) TP7.1
N66771572: BGA1.G14(PR5B/PR8B/PR9B) TP4.1
N66771573: BGA1.G15(PR5A/PR8A/PR9A) TP6.1
N66771601: BGA1.K5(PL12C/PL17C/PL21C) TP1.1
N66771603: BGA1.L4(PL12D/PL17D/PL21D) TP2.1
N66771664: BGA1.C2(PL1D/PL2D/PL2D) TP13.1
N66771666: BGA1.B1(PL1C/PL2C/PL2C) TP11.1
N66771757: BGA1.D2(PL2D/PL4D/PL4D) TP14.1
N66771759: BGA1.C1(PL2C/PL4C/PL4C) TP12.1
N66771796: BGA1.G1(PL6A/PL9A/PL10A) TP5.1
N66862681: R107.1 R117.2 U19.5(A2)
N66863023: R104.2 R118.2 U19.6(A1)
N66863106: R101.2 R116.1 U19.7(A0)
N66867929: R97.2 R120.2 U18.5(A2)
N66867942: R98.2 R119.1 U18.6(A1)
N66868149: R102.1 R121.2 U18.7(A0)

Pads without a net: BGA1 A2 A3 A5 A8 A9 A12 A14 A15 B4 B5 B6 B7 B11 B12 B14 B16 C4 C5 C7 C8 C9 C11 C12 C15 C16 D1 D3 D6 D7 D8 D10 D11 D14 D15 E1 E2 E3 E6 E7 E8 E9 E10 E11 E14 E15 E16 F2 F4 F7 F9 F13 F15 G4 G5 G6 G12 G13 G16 H1 H2 H3 H4 H6 H12 H13 H14 H15 H16 J1 J2 J3 J4 J5 J6 J11 J12 J14 J15 J16 K1 K2 K3 K11 K12 K13 K14 K15 K16 L1 L2 L3 L5 L7 L8 L9 L10 L12 L13 L14 L15 L16 M1 M8 M10 M14 M15 M16 N2 N6 N8 N11 N14 N15 N16 P1 P6 P7 P9 P12 P13 P15 P16 R5 R8 R9 R11 R12 R13 R14 R16 T6 T7 T9 T10 T12 T13 T14 T15; CONN3 4; CONN4 9 10 11 12 14 15; CONN5 9 10 11 12 14 15; CONN6 9 10 11 12 14 15; CONN7 9 10 11 12 14 15; U16 3 5 7 9 11 13 15 17

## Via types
v1: diameter 0.762, hole 0.381, TOP to BOTTOM, 174 vias
v2: diameter 0.457, hole 0.254, TOP to BOTTOM, 83 vias
v3: diameter 0.559, hole 0.305, TOP to BOTTOM, 511 vias
v4: diameter 0.864, hole 0.61, TOP to BOTTOM, 33 vias
v5: diameter 0.508, hole 0.254, TOP to BOTTOM, 9 vias

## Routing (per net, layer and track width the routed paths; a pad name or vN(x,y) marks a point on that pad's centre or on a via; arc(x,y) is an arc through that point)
GND: length 165.4
  TOP w0.381: BGA1.R15 v2(146.13,21.55) ; BGA1.F11 v2(149.33,14.35) ; BGA1.N13 v2(147.73,20.74) ; C33.2 v3(30.45,17.14) ; CONN1.8 v3(32.7,14.08) ; U8.A v3(172.2,24.43) ; C51.1 v3(82.17,5.92) ; U12.A v3(38.8,25.13) ; C8.1 v3(65.33,24.18) ; U4.A v3(97.21,24.74) ; BGA1.D4 v2(155.72,12.75) ; R79.1 v3(113.45,3.87) ; C46.2 v3(136.27,10.51) ; R73.2 v3(181.17,4.31) ; CONN1.13 v3(40.32,7.33) ; C47.2 v3(143.57,5.54) ; R90.2 v3(131.57,6.1) ; R44.1 v3(133.85,27) ; BGA1.M5 v2(154.13,19.94) ; BGA1.J9 v2(150.93,17.54) ; C26.2 v3(140.46,18.8) ; C52.1 v3(249.67,2.43) ; R45.1 v3(203.38,27) ; U15.A v3(236.79,22.86) ; R69.2 v3(175.32,4.31) ; BGA1.L11 v2(149.33,19.14) ; C30.2 32.02,18.56 v3(32.51,19.05) ; C44.2 161.88,3.19 v3(161.48,2.79) ; C15.2 v3(123.49,21.21) ; BGA1.H8 v2(152.52,15.95) ; C23.2 v3(194.23,20.62) ; CONN3.7 v3(100.52,10.08) ; BGA1.E5 v2(154.92,13.55) ; R77.2 v3(187.01,4.31) ; U10.A v3(42.28,25.15) ; OSC1.2 v3(141.15,8.96) ; U6.A v3(104.33,24.73) ; C9.1 v3(133.85,24.18) ; C12.2 v3(52.95,21.21) ; R93.1 v3(252.49,2.43) ; C16.2 v3(191,21.21) ; U14.A v3(233.33,22.86) ; BGA1.N4 v2(155.72,20.74) ; C45.2 v3(136.27,5.23) ; C13.2 v3(54.98,21.21) ; R71.2 v3(178.24,4.31) ; CONN1.1 v3(25.08,7.33) ; BGA1.E12 v2(148.53,13.55) ; CONN1.14 v3(40.32,14.08) ; U16.10 v3(66.28,3.75) ; C50.2 v3(161.1,5.54) ; BGA1.P3 v2(156.52,21.54) ; CONN1.2 24.17,11.76 ; v3(30.86,19.23) C18.2 ; U5.A v3(100.77,24.74) ; BGA1.D13 v2(147.73,12.75) ; BGA1.R2 v2(157.32,21.55) ; U13.A v3(240.3,22.88) ; R43.1 v3(65.33,27) ; C43.2 v3(77.66,9.6) ; BGA1.M12 v2(148.53,19.94) ; CONN1.23 v3(53.02,7.33) ; U9.A v3(175.69,24.43) ; BGA1.B2 v2(156.53,11.15) ; C38.2 v3(246.7,12.78) ; C21.2 v3(56.18,20.62) ; C48.2 v3(144.59,5.54) ; R58.1 v3(108.73,8.58) ; BGA1.C3 v2(156.52,11.95) ; R75.2 v3(184.09,4.31) ; BGA1.C14 v2(146.93,11.95) ; C41.2 v3(246.11,11.57) ; BGA1.F6 v2(154.12,14.35) ; CONN1.9 v3(35.24,7.33) ; C29.2 v3(140.46,17.78) ; C22.2 v3(124.7,20.62) ; CONN1.22 v3(50.48,14.08) ; BGA1.J8 v2(152.52,17.54) ; CONN1.7 v3(32.7,7.33) ; U11.A v3(35.29,25.13) ; CONN1.11 v3(37.78,7.33) ; BGA1.L6 v2(153.33,19.14) ; BGA1.H9 v2(150.93,15.95) ; BGA1.B15 v2(146.13,11.15) ; C14.2 v3(121.46,21.21) ; CONN1.24 v3(53.93,11.76) ; C31.2 v3(140.46,16.76) ; C17.2 v3(193.03,21.21) ; C35.2 v3(246.7,14.81) ; BGA1.P14 v2(146.93,21.54) ; C10.1 v3(203.38,24.18) ; U7.A v3(168.69,24.43)
  TOP w0.508: 12.71,11.35 CONN2.2 ; CONN2.2 13,12.25 ; CONN2.2 13,10.45 ; CONN2.2 14.8,12.25 ; CONN2.2 13.9,10.16 ; CONN2.2 15.09,11.35 ; CONN2.2 14.8,10.45 ; CONN2.2 13.9,12.54 ; 13.9,4.66 CONN2.4 ; CONN2.4 14.8,6.75 ; CONN2.4 13.9,7.04 ; CONN2.4 13,4.95 ; CONN2.4 14.8,4.95 ; CONN2.4 13,6.75 ; CONN2.4 12.71,5.85 ; CONN2.4 15.09,5.85
  G2 w0.381: CONN2.4 15.09,5.85 ; CONN2.4 12.71,5.85 ; CONN2.4 13.9,4.66 ; CONN2.4 13.9,7.04 ; 12.71,11.35 CONN2.2 ; CONN2.2 13.9,10.16 ; CONN2.2 13.9,12.54 ; CONN2.2 15.09,11.35
  BOTTOM w0.381: C40.2 v2(145.29,20.03) ; v5(129.73,26.22) 129.48,25.98 C6.1 ; v2(156.53,11.15) 156.71,10.97 C37.2 ; v5(61.21,26.22) 61.15,26.16 C5.1 ; v3(233.33,22.86) 233.82,23.34 v1(234.31,23.34) ; R121.1 v3(207.15,5.71) ; v1(124.7,19.83) v3(124.7,20.62) ; v2(156.52,11.95) 156.58,12.01 C25.2 ; C4.2 155.61,12.64 v2(155.72,12.75) ; v2(149.33,19.14) 149.34,19.15 C11.2 ; C7.1 198.98,25.94 v5(199.26,26.22) ; v2(154.12,14.35) 154.06,14.41 C24.2 ; v2(147.73,12.75) 147.42,13.06 C28.2 ; R101.1 v3(44.45,6.6) ; v3(65.33,24.18) 65.43,24.18 v1(65.96,23.65) ; C32.2 149.22,14.24 v2(149.33,14.35) ; R98.1 v3(207.15,7.49) v1(207.94,7.49) ; v3(42.28,25.15) 42.3,25.17 v1(43.13,25.17) ; C2.2 153.36,19.17 v2(153.33,19.14) ; C3.2 150.98,15.9 v2(150.93,15.95) ; C42.1 v3(254.56,8.26) ; C39.2 146.07,11.21 v2(146.13,11.15) ; R120.1 v3(207.14,9.27) ; U18.4 v3(197.43,7.58) ; v1(78.51,9.6) v3(77.66,9.6) ; v2(154.91,18.34) 155.02,18.44 C34.2 ; v2(157.32,21.55) 157.34,21.57 C19.2 ; v2(147.73,18.34) 147.94,18.12 C20.2 ; R118.1 v3(44.45,4.83) ; v1(184.09,3.51) v3(184.09,4.31) ; v1(245.32,11.57) v3(246.11,11.57) ; R117.1 v3(44.45,3.05) ; C36.2 v2(147.73,15.94) ; v2(150.93,17.54) 151.3,17.17 C1.2 ; v1(194.23,19.83) v3(194.23,20.62) ; v1(139.67,17.78) v3(140.46,17.78) ; v2(146.13,21.55) 145.93,21.35 C49.2 ; U19.4 v3(52.1,3.56)
  BOTTOM w0.508: 13,10.45 CONN2.2 ; CONN2.2 13.9,10.16 ; CONN2.2 12.71,11.35 ; CONN2.2 13.9,12.54 ; CONN2.2 13,12.25 ; CONN2.2 14.8,10.45 ; CONN2.2 14.8,12.25 ; CONN2.2 15.09,11.35 ; CONN2.4 14.8,6.75 ; CONN2.4 12.71,5.85 ; CONN2.4 13,6.75 ; CONN2.4 13.9,4.66 ; CONN2.4 14.8,4.95 ; CONN2.4 13.9,7.04 ; CONN2.4 13,4.95 ; CONN2.4 15.09,5.85
  vias: v1(18.22,17.08) v1(21.27,4.25) v1(22.02,8.64) v1(24.41,14.91) v1(29.44,18.95) v2(249.68,6.54) v2(250.7,6.54) v2(251.71,6.54) v3(1.35,37.8) v3(1.33,36.13) v3(1.33,31.69) v3(1.33,25.02) v3(1.33,16.64) v3(1.33,12.45) v3(1.33,8.89) v3(1.33,5.4) v3(1.33,1.33) v3(1.65,28.38) v3(6.54,1.33) v3(7.87,40.31) v3(11.11,1.33) v3(15.3,1.33) v3(15.68,40.32) v3(18.41,40.32) v3(18.54,1.65) v3(21.78,1.33) v3(22.16,40.32) v3(22.16,35.5) v3(22.16,31.43) v3(22.17,11.76) v3(22.86,29.15) v3(24.83,28.32) v3(25.59,1.33) v3(29.21,28.32) v3(29.4,1.33) v3(33.21,1.33) v3(33.59,28.32) v3(35.88,29.4) v3(36.39,31.62) v3(36.7,1.33) v3(40.77,1.33) v3(45.59,1.33) v3(46.53,34.23) v3(47.61,34.23) v3(50.23,1.33) v3(54.15,34.23) v3(54.86,1.33) v3(55.23,34.23) v3(55.18,31.11) v3(57.91,28.32) v3(59.75,1.33) v3(62.93,28.32) v3(64.33,1.33) v3(67.25,28.32) v3(69.15,29.08) v3(69.53,1.33) v3(69.85,37.8) v3(69.85,35.56) v3(69.85,30.92) v3(74.1,1.33) v3(76.33,40.31) v3(79.5,1.33) v3(84.39,40.32) v3(84.84,1.33) v3(86.11,40.32) v3(90.23,1.33) v3(90.68,40.32) v3(90.68,35.62) v3(90.68,31.05) v3(91.38,29.08) v3(93.34,28.32) v3(93.54,1.65) v3(96.77,1.33) v3(97.92,28.32) v3(102.11,28.32) v3(102.11,1.33) v3(104.01,28.96) v3(104.84,31.69) v3(108.65,1.33) v3(115.03,34.23) v3(115.19,1.33) v3(116.11,34.23) v3(121.09,1.33) v3(122.65,34.23) v3(123.73,34.23) v3(123.7,31.18) v3(124.4,29.15) v3(126.49,28.32) v3(128.71,1.33) v3(130.75,28.32) v3(135.57,28.32) v3(136.97,1.33) v3(138.35,37.8) v3(138.37,35.37) v3(138.37,30.92) v3(144.72,1.33) v3(144.96,40.31) v3(150.69,1.33) v3(152.21,40.32) v3(157.92,1.33) v3(159.13,40.32) v3(159.19,35.69) v3(159.19,31.18) v3(161.99,28.32) v3(165.23,1.33) v3(166.56,28.32) v3(168.59,1.65) v3(170.62,28.32) v3(171.77,1.33) v3(172.66,29.08) v3(173.35,31.81) v3(176.66,1.33) v3(182.18,1.33) v3(183.53,34.23) v3(184.61,34.23) v3(188.15,1.33) v3(191.15,34.23) v3(192.23,34.23) v3(192.21,31.24) v3(192.91,29.08) v3(194.31,1.33) v3(195.01,28.32) v3(199.58,28.32) v3(200.66,1.33) v3(204.09,28.32) v3(206.06,29.02) v3(206.57,1.33) v3(206.82,35.31) v3(206.88,37.59) v3(206.88,30.99) v3(212.66,1.33) v3(213.49,40.26) v3(218,1.33) v3(220.79,40.32) v3(224.03,1.33) v3(227.65,40.26) v3(227.71,35.81) v3(227.71,31.24) v3(228.41,29.08) v3(229.55,1.33) v3(230.63,28.32) v3(234.95,1.33) v3(235.14,28.32) v3(239.08,28.32) v3(240.28,1.33) v3(241.11,29.08) v3(241.87,32) v3(243.52,1.65) v3(246.76,1.33) v3(252.03,34.23) v3(253.11,34.23) v3(253.94,1.33) v3(259.65,34.23) v3(260.41,28.32) v3(260.73,34.23) v3(260.73,31.69) v3(260.73,25.15) v3(260.73,21.4) v3(260.73,17.46) v3(260.73,13.27) v3(260.73,9.46) v3(260.73,5.21) v3(260.67,1.33) v4(15.43,12.06) v4(15.43,8.83) v4(16,5.59) v4(17.27,13.27) v4(18.92,14.54) v4(19.43,17.65) v4(19.56,15.75) v4(20.95,14.54) v4(22.92,17.02) v4(22.92,15.68) v4(26.42,18.54) v4(26.67,16.76) v4(28.07,17.4) v5(61.21,25.21) v5(61.21,24.19) v5(129.73,25.21) v5(129.73,24.19) v5(199.26,25.21) v5(199.26,24.19)
VCC_12P_FAN1: length 0.9
  BOTTOM w0.381: v3(187.83,34.15) v1(187.83,33.25)
VCC_12P_FAN2: length 0.9
  BOTTOM w0.381: v3(119.33,34.16) v1(119.33,33.26)
VCC_12P_FAN3: length 0.9
  BOTTOM w0.381: v3(50.83,34.16) v1(50.83,33.26)
VCC_12P_FAN4: length 0.9
  BOTTOM w0.381: v3(256.33,34.16) v1(256.33,33.26)
VCC_CL_FAN1: length 0.8
  BOTTOM w0.203: v1(200.83,25.02) 201.62,25.02 v3(201.62,25.02)
VCC_CL_FAN2: length 0.8
  BOTTOM w0.203: v3(132.09,25.02) 132.09,25.02 v1(131.3,25.02)
VCC_CL_FAN3: length 0.8
  BOTTOM w0.203: v3(63.58,25.02) 63.58,25.03 v1(62.79,25.03)
VCC_CL_FAN4: length 0.8
  BOTTOM w0.203: v1(250.51,4.97) v3(250.51,4.18)
VDD12V: length 67.3
  TOP w0.381: v3(245.95,9.12) 246.11,9.28 C41.1 ; C22.1 v3(127.46,20.62) ; v3(58.64,20.54) 58.55,20.62 C21.1 ; C23.1 196.6,20.62 v3(196.67,20.55)
  TOP w0.508: 8.51,10.16 CONN2.1 ; CONN2.1 9.7,12.54 ; CONN2.1 10.89,12.54 ; CONN2.1 10.89,10.16 ; CONN2.1 8.51,11.35 ; CONN2.1 8.51,12.54 ; CONN2.1 9.7,10.16 ; CONN2.1 10.89,11.35 ; CONN2.3 9.7,7.04 ; CONN2.3 8.8,6.75 ; CONN2.3 10.89,5.85 ; CONN2.3 9.7,4.66 ; CONN2.3 10.6,6.75 ; CONN2.3 8.51,5.85 ; CONN2.3 8.8,4.95 ; CONN2.3 10.6,4.95 ; v4(31.5,21.21) 31.56,21.15 C18.1
  V3 w0.508: 8.51,11.35 CONN2.1 ; CONN2.1 9.7,12.54 ; CONN2.1 8.8,12.25 ; CONN2.1 10.6,12.25 ; CONN2.1 10.89,11.35 ; CONN2.1 9.7,10.16 ; CONN2.1 10.6,10.45 ; CONN2.1 8.8,10.45 ; CONN2.3 10.6,4.95 ; CONN2.3 8.8,4.95 ; CONN2.3 10.89,5.85 ; CONN2.3 9.7,4.66 ; CONN2.3 8.8,6.75 ; CONN2.3 10.6,6.75 ; CONN2.3 9.7,7.04 ; CONN2.3 8.51,5.85
  BOTTOM w0.381: v3(245.29,8.43) v1(244.49,8.43) ; v3(129.54,20.57) v1(129.54,21.37)
  BOTTOM w0.508: 8.51,5.85 CONN2.3 ; CONN2.3 10.6,6.75 ; CONN2.3 10.89,5.85 ; CONN2.3 10.6,4.95 ; CONN2.3 8.8,4.95 ; CONN2.3 8.8,6.75 ; CONN2.3 9.7,7.04 ; CONN2.3 9.7,4.66 ; 8.8,12.25 CONN2.1 ; CONN2.1 9.7,12.54 ; CONN2.1 9.7,10.16 ; CONN2.1 10.89,11.35 ; CONN2.1 10.6,10.45 ; CONN2.1 10.6,12.25 ; CONN2.1 8.8,10.45 ; CONN2.1 8.51,11.35
  vias: v1(18.16,23.56) v1(24.32,23.18) v1(159.38,26.29) v3(58.48,22.48) v3(58.48,21.46) v3(59.23,19.84) v3(59.44,22.48) v3(59.44,21.46) v3(59.77,20.6) v3(60.38,19.91) v3(61.02,20.57) v3(127,22.48) v3(127,21.46) v3(127.91,19.81) v3(127.95,22.48) v3(127.95,21.46) v3(128.5,20.57) v3(129.01,19.81) v3(155.13,26.67) v3(155.13,25.72) v3(156.4,26.67) v3(156.4,25.72) v3(157.54,26.67) v3(157.54,25.72) v3(161.42,26.61) v3(161.42,25.53) v3(162.5,26.61) v3(162.5,25.53) v3(163.51,26.61) v3(163.51,25.53) v3(196.53,22.48) v3(196.53,21.46) v3(197.28,19.86) v3(197.49,22.48) v3(197.49,21.46) v3(197.92,20.55) v3(198.5,19.84) v3(199.07,20.57) v3(245.31,7.26) v3(246.02,7.85) v3(246.06,6.73) v3(246.95,9.27) v3(246.95,8.32) v3(247.97,9.27) v3(247.97,8.32) v4(7.81,13.97) v4(9.91,13.97) v4(11.62,15.24) v4(12.57,13.97) v4(13.72,15.24) v4(13.84,16.89) v4(15.43,22.23) v4(15.43,20.45) v4(15.37,16.89) v4(15.37,15.24) v4(16.07,23.43) v4(19.43,21.84) v4(20.83,22.99) v4(22.73,21.59) v4(22.86,22.99) v4(26.42,21.72) v4(27.18,22.99) v4(28.96,23.24) v4(31.35,22.85)
25MHZ_EN: length 3.2
  TOP w0.203: OSC1.1 140.11,6.15 139.77,5.81 R65.2 v3(139.77,4.55)
  BOTTOM w0.203: v1(139.19,5.12) v3(139.77,4.55)
BOARD_ID_1: length 31.9
  TOP w0.152: 158.31,14.12 158.15,14.12 157.95,14.33 156.54,14.33 BGA1.F3
  TOP w0.203: v3(179.71,7.51) R72.2 R71.1 ; v3(160.46,13.21) 159.55,14.12 158.31,14.12
  BOTTOM w0.203: v3(179.71,7.51) v1(179.71,8.32) 179.71,9.21 173.23,15.68 163.77,15.68 161.29,13.21 v3(160.46,13.21)
BOARD_ID_2: length 32.3
  TOP w0.203: v3(182.63,7.51) R74.2 R73.1 ; v3(160.37,14.26) 159.96,14.67 157.8,14.67 BGA1.F1
  BOTTOM w0.203: v3(182.63,7.51) v1(182.63,8.32) 174.69,16.26 163.32,16.26 161.32,14.26 v3(160.37,14.26)
CPLD_25MHZ: length 8.3
  TOP w0.203: BGA1.D16 143.09,10.5 v3(140.34,10.5) R67.1
  BOTTOM w0.203: v1(139.45,10.39) 140.22,10.39 v3(140.34,10.5)
CPLD_25MHZ_R: length 3.1
  TOP w0.203: OSC1.3 138.51,9.97 138.54,10 R67.2 v3(138.54,11.2)
  BOTTOM w0.203: v1(137.73,11.2) v3(138.54,11.2)
CPLD_TCK: length 5.5
  TOP w0.203: BGA1.A7 152.92,9.68 153.12,9.48 v3(153.12,6.78) R86.1
  BOTTOM w0.203: v1(153.12,7.59) v3(153.12,6.78)
CPLD_TDI: length 6.1
  TOP w0.203: R87.1 v3(155.15,6.78) 155.15,9.32 BGA1.A6
  BOTTOM w0.203: v1(155.15,7.59) v3(155.15,6.78)
CPLD_TDO: length 8.5
  TOP w0.152: BGA1.C6 154.12,11.95 154.72,11.95 154.92,11.75 154.92,10.46 155.16,10.22
  TOP w0.203: R88.1 v3(156.17,6.78) 156.17,9.21 155.16,10.22
  BOTTOM w0.203: v1(156.54,7.48) 156.54,7.15 v3(156.17,6.78)
CPLD_TMS: length 7.4
  TOP w0.152: 152.36,10.22 152.36,10.39 152.53,10.55 152.53,11.14 BGA1.B8
  TOP w0.203: R85.1 v3(152.11,6.78) 152.36,7.04 152.36,10.22
  BOTTOM w0.203: v1(152.11,8.36) v3(152.11,6.78)
CPLD_UPD_DISABLE: length 106.7
  TOP w0.203: BGA1.A4 v2(155.72,10.35) ; v3(63.91,9.6) R66.2 64.71,9.61 U16.1
  BOTTOM w0.203: v2(155.72,10.35) 150.84,10.35 148.98,8.48 142.89,8.48 142.1,7.7 138.79,7.7 138.77,7.72 134.85,7.72 132.72,9.85 132.72,13.1 130.97,14.86 91.5,14.86 83.78,7.14 79.77,7.14 79.01,6.38 72.15,6.38 70.77,7.75 70.36,7.75 v1(68.66,9.45) 68.51,9.6 v3(63.91,9.6)
EN_FAN1: length 48.1
  TOP w0.203: v3(196.91,25.9) 197.11,25.71 U3.7 ; BGA1.H5 v2(154.92,15.95)
  BOTTOM w0.203: v2(154.92,15.95) 158.85,19.88 188.09,19.88 193,24.79 v1(196.19,24.79) R48.2 196.72,25.71 v3(196.91,25.9)
EN_FAN2: length 33.7
  TOP w0.203: BGA1.T4 v2(155.32,23.88) ; v3(127.39,25.85) 127.53,25.71 U2.7
  BOTTOM w0.203: R47.2 127.25,25.7 v3(127.39,25.85) v1(127.39,24.64) 127.77,24.26 128.43,24.26 129.07,23.62 134.24,23.62 135.99,25.37 151.03,25.37 152.53,23.88 v2(155.32,23.88)
EN_FAN3: length 102.3
  TOP w0.203: U1.7 59.07,25.71 v3(58.88,25.9) ; BGA1.N9 v2(151.72,20.74)
  BOTTOM w0.203: v2(151.72,20.74) 151.72,21.51 149.5,23.72 137.95,23.72 132.79,18.57 120.12,18.57 117.6,21.08 63.09,21.08 v1(60.71,23.47) 58.88,25.3 v3(58.88,25.9) 58.69,25.71 R46.2
EN_FAN4: length 107.3
  TOP w0.203: v3(251.39,8.87) 251.2,8.68 U17.7 ; BGA1.K6 v2(154.12,17.55)
  BOTTOM w0.203: R64.2 251.39,9.58 v3(251.39,8.87) 251.38,8.88 v1(250.41,8.88) 248.87,10.41 242.25,10.41 233.74,18.92 193.23,18.92 192.68,19.47 159.74,19.47 155.68,15.41 154.69,15.41 154.33,15.77 154.33,17.34 v2(154.12,17.55)
FAN1_DET: length 43.3
  TOP w0.203: R14.2 v3(190.96,30.79) ; BGA1.R4 v2(155.72,22.34)
  BOTTOM w0.203: v3(190.96,30.79) v1(190.13,29.96) 190.02,29.84 182.64,29.84 178.69,25.89 178.69,23.67 175.91,20.89 165.82,20.89 163.42,23.29 157.54,23.29 156.59,22.34 v2(155.72,22.34)
FAN1_DET_R: length 32.1
  TOP w0.203: R112.1 R14.1 v3(190.96,33.08) ; U9.C1 v3(174.74,22.43)
  BOTTOM w0.203: CONN6.16 191.68,33.81 v3(190.96,33.08) 190.17,32.29 179.14,32.29 178.32,31.48 178.32,29.9 174.74,26.32 v1(174.74,23.22) v3(174.74,22.43)
FAN1_DIR: length 35.7
  TOP w0.203: BGA1.T3 v2(156.12,23.3) ; R13.2 v3(184.04,30.79)
  BOTTOM w0.203: v2(156.12,23.3) 156.5,23.3 156.79,23.6 v1(156.81,23.6) 157.01,23.8 163.72,23.8 166.12,21.4 175.63,21.4 178.08,23.85 178.08,26.33 182.54,30.79 v3(184.04,30.79)
FAN1_DIR_R: length 20.1
  TOP w0.203: R13.1 183.68,32.37 183.16,31.85 183.16,29.83 U9.C2 ; R13.1 R108.1 ; R13.1 v3(184.04,33.05)
  BOTTOM w0.203: v1(183.23,33.05) v3(184.04,33.05) 184.06,33.07 CONN6.13
FAN1_IN_PWM: length 22.1
  TOP w0.203: CONN6.4 181.52,33.07 181.5,33.04 R34.2 181.88,32.37 182.22,32.03 182.22,30.94 179.74,28.46 176.52,28.46 173.15,25.09 v3(173.15,24.18) U8.C2
  BOTTOM w0.203: v1(173.15,23.37) v3(173.15,24.18)
FAN1_LED_G: length 18.2
  TOP w0.152: 154.69,23.37 154.94,23.11 154.94,22.61 154.67,22.34 154.12,22.34 BGA1.R6
  TOP w0.203: v1(148.84,35.81) v3(148.84,34.8) 148.84,30.73 154.43,25.15 154.43,23.62 154.69,23.37
  BOTTOM w0.203: v1(148.84,35.81) v3(148.84,34.8)
FAN1_LED_G_R: length 3.9
  TOP w0.203: LED3.C2 v3(148.77,38.35) 148.77,37.41 v1(148.84,37.34)
  BOTTOM w0.203: v1(148.84,37.34) 148.84,38.28 v3(148.77,38.35)
FAN1_LED_R: length 17.3
  TOP w0.203: v1(146.81,35.81) v3(146.81,34.8) 146.81,31.98 153.92,24.87 153.92,23.35 BGA1.T5
  BOTTOM w0.203: v1(146.81,35.81) v3(146.81,34.8)
FAN1_LED_R_R: length 4.7
  TOP w0.203: v1(146.81,37.34) 147.02,37.55 v3(147.02,38.35) LED3.C1
  BOTTOM w0.203: v3(147.02,38.35) 146.81,38.14 v1(146.81,37.34)
FAN1_OUT_PWM: length 20.8
  TOP w0.203: CONN6.3 178.98,33.12 178.91,33.04 178.91,32.42 R33.2 178.7,32.37 178.33,32 178.33,30.61 177.61,29.88 176.87,29.88 173.53,26.54 171.86,26.54 171.25,25.93 v3(171.25,24.18) U8.C1
  BOTTOM w0.203: v1(171.25,23.37) v3(171.25,24.18)
FAN1_PWM: length 37.9
  TOP w0.203: BGA1.P4 v2(155.72,21.54) ; R34.1 R33.1 v3(178.96,30.78)
  BOTTOM w0.203: v2(155.72,21.54) 155.42,21.84 v1(155.05,21.84) 155.05,22.94 156.36,24.26 164.08,24.26 166.5,21.84 175.34,21.84 177.29,23.8 177.29,27.28 178.96,28.94 v3(178.96,30.78)
FAN1_SENSOR: length 24.6
  TOP w0.203: R31.2 v3(176.7,30.78) 172.95,27.03 167.89,27.03 164.11,23.24 157.42,23.24 BGA1.T2
  BOTTOM w0.203: v1(176.7,29.97) v3(176.7,30.78)
FAN1_SENSOR_R: length 21.6
  TOP w0.203: R32.1 R31.1 v3(176.7,33.04) 176.44,33.3 CONN6.2 ; U7.C2 v3(169.64,22.43)
  BOTTOM w0.203: v3(176.7,33.04) 176.15,32.49 176.15,30.37 169.64,23.86 v1(169.64,23.22) v3(169.64,22.43)
FAN1_VCP: length 3.7
  TOP w0.203: v3(203.38,25.09) C10.2 202.07,25.71 U3.4
  BOTTOM w0.203: v1(202.57,25.09) v3(203.38,25.09)
FAN1R_SENSOR: length 24.8
  TOP w0.152: 156.54,22.97 156.54,22.36 BGA1.R3
  TOP w0.203: 156.54,22.97 157.26,23.69 163.77,23.69 167.51,27.43 172.31,27.43 174.63,29.75 v3(174.63,30.78) R29.2
  BOTTOM w0.203: v3(174.63,30.78) 174.63,30.88 v1(175.26,31.5)
FAN1R_SENSOR_R: length 22.5
  TOP w0.203: CONN6.1 173.9,34.5 174.63,33.78 v3(174.63,33.04) R29.1 R30.1 ; U7.C1 v3(166.9,23.31)
  BOTTOM w0.203: v3(166.9,23.31) v1(166.9,24.1) 169.37,26.57 171.58,26.57 174.09,29.08 174.09,32.5 v3(174.63,33.04)
FAN2_DET: length 40.3
  TOP w0.203: R12.2 v3(122.47,30.79) ; BGA1.P5 v2(154.13,21.54)
  BOTTOM w0.203: v2(154.13,21.54) 150.7,24.97 136.32,24.97 134.49,23.14 128.93,23.14 128.31,23.76 126.04,23.76 v1(122.68,27.11) 122.47,27.33 v3(122.47,30.79)
FAN2_DET_R: length 31.5
  TOP w0.203: R113.1 R12.1 v3(122.47,33.05) ; U6.C1 v3(103.38,22.72)
  BOTTOM w0.203: CONN5.16 123.18,33.77 v3(122.47,33.05) 121.88,32.46 114.81,32.46 105.07,22.72 v1(104.17,22.72) v3(103.38,22.72)
FAN2_DIR: length 47
  TOP w0.203: R11.2 v3(115.57,30.79) ; BGA1.M6 v2(153.33,19.94)
  BOTTOM w0.203: v2(153.33,19.94) 153.85,20.46 153.85,21.01 150.29,24.56 136.63,24.56 134.77,22.71 128.75,22.71 128.17,23.29 122.06,23.29 v1(116.2,29.15) 115.57,29.78 v3(115.57,30.79)
FAN2_DIR_R: length 21.7
  TOP w0.203: R109.1 R11.1 v3(115.57,33.05) ; U6.C2 v3(105.28,24.48)
  BOTTOM w0.203: v3(105.28,24.48) 105.88,24.48 v1(106.06,24.65) 114.45,33.05 v3(115.57,33.05) 115.56,33.05 CONN5.13
FAN2_IN_PWM: length 22.2
  TOP w0.203: R28.2 113,32.86 113.02,32.88 v3(113.02,33.04) CONN5.4 ; U5.C2 v3(101.72,24.49)
  BOTTOM w0.203: v3(101.72,24.49) v1(102.51,24.49) 103.35,25.32 105.92,25.32 113.02,32.43 v3(113.02,33.04)
FAN2_LED_G: length 87.3
  TOP w0.203: v1(80.26,35.81) v3(80.26,34.8) 80.26,31.67 82.32,29.62 87.4,29.62 99.16,17.86 133.9,17.86 141.41,25.37 150.16,25.37 151.82,23.72 151.82,23.05 BGA1.T8
  BOTTOM w0.203: v1(80.26,35.81) v3(80.26,34.8)
FAN2_LED_G_R: length 3.9
  TOP w0.203: v1(80.26,37.34) 80.27,37.35 v3(80.27,38.35) LED2.C2
  BOTTOM w0.203: v1(80.26,37.34) 80.26,38.34 v3(80.27,38.35)
FAN2_LED_R: length 90.5
  TOP w0.152: 150.93,23.37 150.93,21.74 151.12,21.55 151.72,21.55 BGA1.P8
  TOP w0.203: 150.93,23.37 150.93,23.85 149.81,24.97 141.71,24.97 133.88,17.14 98.93,17.14 87.12,28.96 82.04,28.96 78.23,32.77 v3(78.23,34.8) v1(78.23,35.81)
  BOTTOM w0.203: v1(78.23,35.81) v3(78.23,34.8)
FAN2_LED_R_R: length 4.7
  TOP w0.203: R6.1 78.52,37.63 v3(78.52,38.35) LED2.C1
  BOTTOM w0.203: v1(78.49,37.34) 78.49,38.32 v3(78.52,38.35)
FAN2_OUT_PWM: length 22.7
  TOP w0.203: CONN5.3 110.48,33.12 v3(110.41,33.04) 110.46,32.99 R27.2 ; U5.C1 v3(99.82,24.49)
  BOTTOM w0.203: v3(99.82,24.49) 99.82,24.95 v1(100.18,25.31) 100.68,25.81 105.33,25.81 109.88,30.35 109.88,32.51 v3(110.41,33.04)
FAN2_PWM: length 67.3
  TOP w0.152: 153.31,22.97 153.31,22.33 BGA1.R7
  TOP w0.203: 153.31,22.97 153.31,23.98 151.03,26.26 140.84,26.26 133.5,18.92 110.44,18.92 107.59,21.77 107.59,27.94 110.46,30.81 ; 110.46,30.81 R27.1 R28.1 ; 110.46,30.81 v3(110.46,30.78)
  BOTTOM w0.203: v1(111.03,31.35) v3(110.46,30.78)
FAN2_SENSOR: length 66.7
  TOP w0.152: BGA1.M7 152.53,19.94 152.53,23.37
  TOP w0.203: 152.53,23.37 152.53,24 150.7,25.83 141.11,25.83 133.59,18.31 110.31,18.31 106.91,21.72 106.91,28.78 108.3,30.17 v3(108.3,30.78) R25.2
  BOTTOM w0.203: v3(108.3,30.78) 108.75,31.24 v1(108.75,31.43)
FAN2_SENSOR_R: length 26
  TOP w0.203: CONN5.2 107.94,33.39 v3(108.3,33.04) R25.1 R26.1 ; U4.C2 v3(98.16,22.71)
  BOTTOM w0.203: v3(108.3,33.04) 107.7,32.44 107.7,29.01 105.03,26.34 100.22,26.34 98.97,25.09 v1(98.97,22.71) v3(98.16,22.71)
FAN2_VCP: length 3.7
  TOP w0.203: v3(133.85,25.09) C9.2 132.54,25.71 U2.4
  BOTTOM w0.203: v1(133.04,25.09) v3(133.85,25.09)
